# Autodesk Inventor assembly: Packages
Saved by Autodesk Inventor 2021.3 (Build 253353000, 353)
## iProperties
Created: 2021-12
Part Number: Packages
Document SubType Name: Assembly
Designer: Administrator
Title: Packages
Author: Administrator
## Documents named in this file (17)
- c:\worker\convert-fusion-r08\tmp\job-1\42\output\files\5687be83-607c-4978-9340-54991ac6dc59\Packages.iam
- c:\worker\convert-fusion-r08\tmp\job-1\42\output\files\5687be83-607c-4978-9340-54991ac6dc59\ESP32WROOM32D4MBPS.ipt
- c:\worker\convert-fusion-r08\tmp\job-1\42\output\files\5687be83-607c-4978-9340-54991ac6dc59\SOT230P700X180-4N.ipt
- c:\worker\convert-fusion-r08\tmp\job-1\42\output\files\5687be83-607c-4978-9340-54991ac6dc59\SOD123.ipt
- c:\worker\convert-fusion-r08\tmp\job-1\42\output\files\5687be83-607c-4978-9340-54991ac6dc59\DFPLAYER_MINI.ipt
- c:\worker\convert-fusion-r08\tmp\job-1\42\output\files\5687be83-607c-4978-9340-54991ac6dc59\ILI9341_MODULE1.ipt
- c:\worker\convert-fusion-r08\tmp\job-1\42\output\files\5687be83-607c-4978-9340-54991ac6dc59\SOP100P600X150-11T240X280N.ipt
- c:\worker\convert-fusion-r08\tmp\job-1\42\output\files\5687be83-607c-4978-9340-54991ac6dc59\1X02.ipt
- c:\worker\convert-fusion-r08\tmp\job-1\42\output\files\5687be83-607c-4978-9340-54991ac6dc59\1X04.ipt
- c:\worker\convert-fusion-r08\tmp\job-1\42\output\files\5687be83-607c-4978-9340-54991ac6dc59\1X07.ipt
- c:\worker\convert-fusion-r08\tmp\job-1\42\output\files\5687be83-607c-4978-9340-54991ac6dc59\1X02 (1).ipt
- c:\worker\convert-fusion-r08\tmp\job-1\42\output\files\5687be83-607c-4978-9340-54991ac6dc59\2X20.ipt
- c:\worker\convert-fusion-r08\tmp\job-1\42\output\files\5687be83-607c-4978-9340-54991ac6dc59\C1206.ipt
- c:\worker\convert-fusion-r08\tmp\job-1\42\output\files\5687be83-607c-4978-9340-54991ac6dc59\E2,5-7.ipt
- c:\worker\convert-fusion-r08\tmp\job-1\42\output\files\5687be83-607c-4978-9340-54991ac6dc59\M1206.ipt
- c:\worker\convert-fusion-r08\tmp\job-1\42\output\files\5687be83-607c-4978-9340-54991ac6dc59\B3F-10XX.ipt
- c:\worker\convert-fusion-r08\tmp\job-1\42\output\files\5687be83-607c-4978-9340-54991ac6dc59\MSOP8.ipt
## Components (30 placed, 30 different names)
1. ESP32WROOM32D4MBPS:IC1
2. SOT230P700X180-4N:IC4
3. SOD123:D1
4. DFPLAYER_MINI:U$2
5. ILI9341_MODULE1:U$1
6. SOP100P600X150-11T240X280N:IC3
7. 1X02:JP5
8. 1X04:JP3
9. 1X07:JP2
10. 1X02 (1):JP1
11. 2X20:JP4
12. C1206:C5
13. C1206:C6
14. C1206:C1
15. C1206:C2
16. C1206:C7
17. C1206:C8
18. E2,5-7:C3
19. E2,5-7:C4
20. M1206:R1
21. M1206:R2
22. M1206:R3
23. M1206:R4
24. M1206:R5
25. M1206:R6
26. M1206:R7
27. M1206:R8
28. B3F-10XX:S1
29. B3F-10XX:S2
30. MSOP8:T1
